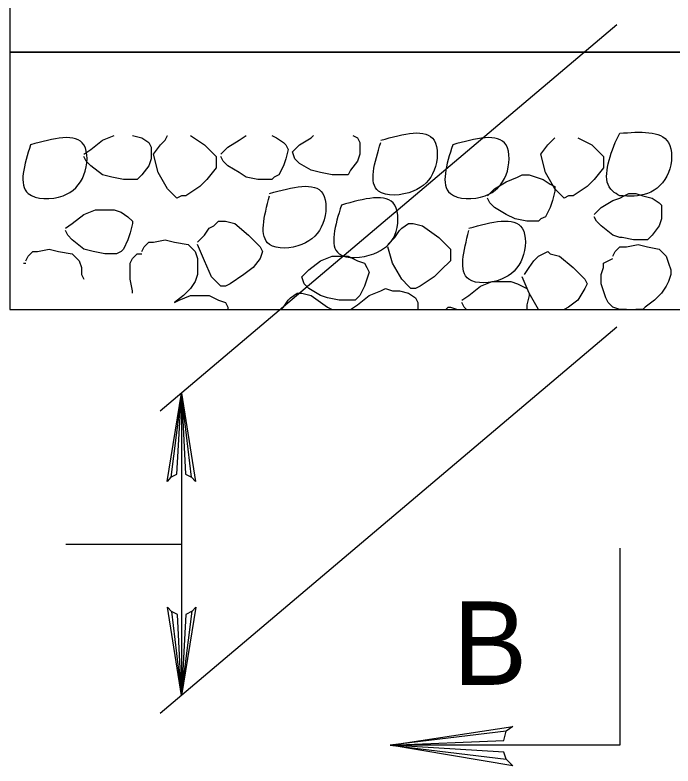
# Model space of a CAD drawing. Extents: x 593 to 1473, y 721 to 1315.
# Drawn here: x 787.25 to 822.71, y 811.39 to 851.89 of the extents above; entities that cross this region are included whole.
import ezdxf

# ---------------------------------------------------------------- set-up
doc = ezdxf.new("R2010")
doc.units = 0
doc.layers.add('1', color=7, linetype='Continuous')
doc.layers.add('2', color=7, linetype='Continuous')

msp = doc.modelspace()

# ---------------------------------------------------------------- linework, layer by layer
at = {"layer": '1'}
for points in [[(795.646, 826.959), (795.975, 827.129), (796.216, 831.5), (795.646, 826.959), (795.447, 826.726), (796.216, 831.5), (796.432, 827.132), (796.757, 826.972), (796.216, 831.5), (796.974, 826.726), (796.757, 826.972)], [(795.646, 826.959), (795.975, 827.129), (796.216, 831.5), (795.646, 826.959), (795.447, 826.726), (796.216, 831.5), (796.432, 827.132), (796.757, 826.972), (796.216, 831.5), (796.974, 826.726), (796.757, 826.972)], [(796.786, 819.732), (796.457, 819.562), (796.216, 815.191), (796.786, 819.732), (796.985, 819.965), (796.216, 815.191), (796, 819.559), (795.675, 819.719), (796.216, 815.191), (795.457, 819.965), (795.675, 819.719)], [(796.786, 819.732), (796.457, 819.562), (796.216, 815.191), (796.786, 819.732), (796.985, 819.965), (796.216, 815.191), (796, 819.559), (795.675, 819.719), (796.216, 815.191), (795.457, 819.965), (795.675, 819.719)]]:
    msp.add_lwpolyline(points, dxfattribs=at)
at = {"layer": '2'}
for p, q in [((819.688, 851.356), (795.071, 830.531)), ((819.584, 845.016), (819.834, 845.516)), ((819.688, 835.048), (795.071, 814.222)), ((796.216, 831.5), (796.216, 815.191)), ((789.993, 823.346), (796.216, 823.346)), ((819.834, 823.141), (819.834, 812.516)), ((819.834, 812.516), (807.459, 812.516))]:
    msp.add_line(p, q, dxfattribs=at)
for points in [[(786.959, 856.891), (786.959, 849.891), (819.834, 849.891)], [(819.834, 849.891), (854.709, 849.891), (854.709, 856.641)], [(819.834, 849.891), (786.959, 849.891), (786.959, 836.016), (819.834, 836.016)], [(819.834, 836.016), (854.709, 836.016), (854.709, 849.891), (819.834, 849.891)], [(791.959, 845.141), (792.584, 845.391)], [(793.584, 845.391), (794.084, 845.266)], [(794.084, 845.266), (794.459, 845.016)], [(795.334, 845.141), (795.459, 845.391)], [(795.459, 845.391), (795.459, 845.391)], [(796.709, 845.391), (797.459, 844.891)], [(799.334, 845.141), (799.709, 845.391)], [(801.084, 845.391), (801.334, 845.266)], [(801.334, 845.266), (801.709, 845.016)], [(802.584, 844.891), (803.209, 845.266)], [(803.209, 845.266), (803.334, 845.391)], [(805.459, 845.391), (805.709, 845.266)], [(805.709, 845.266), (805.834, 845.016)], [(816.209, 845.141), (816.334, 845.266)], [(817.584, 845.266), (818.334, 844.891)], [(791.334, 844.641), (791.959, 845.141)], [(794.459, 845.016), (794.584, 844.766)], [(794.709, 844.391), (795.084, 844.891)], [(795.084, 844.891), (795.334, 845.141)], [(797.459, 844.891), (798.084, 844.266)], [(798.709, 844.766), (799.334, 845.141)], [(801.709, 845.016), (801.834, 844.891)], [(801.834, 844.891), (801.959, 844.641)], [(802.209, 844.516), (802.584, 844.891)], [(805.834, 845.016), (805.834, 844.766)], [(815.584, 844.391), (815.959, 844.891)], [(815.959, 844.891), (816.209, 845.141)], [(818.334, 844.891), (818.959, 844.266)], [(790.959, 844.391), (791.334, 844.641)], [(794.584, 844.766), (794.584, 844.641)], [(794.584, 844.641), (794.584, 844.141)], [(798.334, 844.391), (798.709, 844.766)], [(801.959, 844.641), (801.834, 844.141)], [(802.334, 844.141), (802.209, 844.516)], [(805.834, 844.766), (805.834, 844.391)], [(791.084, 844.016), (790.959, 844.266)], [(794.584, 844.141), (794.459, 843.766)], [(794.959, 843.391), (794.709, 844.391)], [(798.084, 844.266), (798.084, 843.891)], [(798.459, 844.016), (798.334, 844.266)], [(801.834, 844.141), (801.709, 843.766)], [(802.584, 843.891), (802.334, 844.141)], [(805.834, 844.391), (805.709, 844.016)], [(815.834, 843.391), (815.584, 844.391)], [(818.959, 844.266), (818.959, 843.891)], [(791.334, 843.766), (791.084, 844.016)], [(791.959, 843.266), (791.334, 843.766)], [(794.459, 843.766), (794.084, 843.266)], [(798.084, 843.641), (797.584, 843.016)], [(798.084, 843.891), (798.084, 843.641)], [(798.709, 843.766), (798.459, 844.016)], [(799.334, 843.391), (798.709, 843.766)], [(801.709, 843.766), (801.459, 843.266)], [(803.209, 843.516), (802.584, 843.891)], [(805.709, 844.016), (805.334, 843.516)], [(818.959, 843.641), (818.459, 843.016)], [(818.959, 843.891), (818.959, 843.641)], [(792.459, 843.141), (791.959, 843.266)], [(794.084, 843.266), (793.959, 843.141)], [(795.459, 842.516), (794.959, 843.391)], [(799.709, 843.141), (799.334, 843.391)], [(801.459, 843.266), (801.209, 843.141)], [(803.709, 843.391), (803.209, 843.516)], [(804.334, 843.266), (803.709, 843.391)], [(805.084, 843.266), (804.334, 843.266)], [(805.209, 843.266), (805.084, 843.266)], [(805.334, 843.516), (805.209, 843.266)], [(814.334, 843.141), (814.584, 843.266)], [(814.584, 843.266), (814.959, 843.266)], [(814.959, 843.266), (815.334, 843.141)], [(816.334, 842.516), (815.834, 843.391)], [(793.084, 843.016), (792.459, 843.141)], [(793.834, 843.016), (793.084, 843.016)], [(793.959, 843.141), (793.834, 843.016)], [(797.584, 843.016), (797.209, 842.641)], [(800.334, 843.016), (799.709, 843.141)], [(801.084, 843.016), (800.334, 843.016)], [(801.209, 843.141), (801.084, 843.016)], [(813.084, 842.516), (813.709, 842.891)], [(813.709, 842.891), (814.334, 843.141)], [(815.334, 843.141), (815.709, 843.016)], [(815.709, 843.016), (816.084, 842.766)], [(818.459, 843.016), (818.084, 842.641)], [(795.834, 842.141), (795.459, 842.516)], [(797.209, 842.641), (796.459, 842.141)], [(812.709, 842.141), (813.084, 842.516)], [(816.084, 842.766), (816.334, 842.641)], [(816.334, 842.641), (816.334, 842.391)], [(816.709, 842.141), (816.334, 842.516)], [(818.084, 842.641), (817.334, 842.141)], [(795.959, 842.016), (795.834, 842.141)], [(796.209, 842.141), (795.959, 842.016)], [(796.459, 842.141), (796.209, 842.141)], [(812.834, 841.766), (812.709, 842.016)], [(816.334, 842.391), (816.209, 841.891)], [(816.834, 842.016), (816.709, 842.141)], [(817.084, 842.141), (816.834, 842.016)], [(817.334, 842.141), (817.084, 842.141)], [(819.459, 841.891), (819.834, 842.016)], [(819.834, 842.016), (820.084, 842.141)], [(820.084, 842.141), (820.334, 842.266)], [(820.334, 842.266), (820.709, 842.266)], [(820.709, 842.266), (821.084, 842.141)], [(821.084, 842.141), (821.584, 842.016)], [(821.584, 842.016), (821.959, 841.766)], [(813.084, 841.516), (812.834, 841.766)], [(816.209, 841.891), (816.084, 841.516)], [(818.834, 841.516), (819.459, 841.891)], [(821.959, 841.766), (822.084, 841.641)], [(822.084, 841.641), (822.084, 841.391)], [(790.959, 841.141), (791.584, 841.391)], [(791.584, 841.391), (791.834, 841.391)], [(791.834, 841.391), (792.209, 841.391)], [(792.209, 841.391), (792.584, 841.391)], [(792.584, 841.391), (792.959, 841.266)], [(792.959, 841.266), (793.334, 841.016)], [(813.709, 841.141), (813.084, 841.516)], [(816.084, 841.516), (815.834, 841.016)], [(818.459, 841.141), (818.834, 841.516)], [(822.084, 841.391), (822.084, 840.891)], [(790.334, 840.641), (790.959, 841.141)], [(793.334, 841.016), (793.584, 840.766)], [(814.209, 840.891), (813.709, 841.141)], [(814.834, 840.766), (814.209, 840.891)], [(815.584, 840.891), (815.459, 840.766)], [(815.834, 841.016), (815.584, 840.891)], [(818.584, 840.766), (818.459, 841.016)], [(822.084, 840.891), (821.959, 840.516)], [(789.959, 840.391), (790.334, 840.641)], [(793.584, 840.641), (793.459, 840.141)], [(793.584, 840.766), (793.584, 840.641)], [(797.459, 840.016), (797.709, 840.391)], [(797.709, 840.391), (797.959, 840.516)], [(797.959, 840.516), (798.209, 840.766)], [(798.209, 840.766), (798.334, 840.766)], [(798.334, 840.766), (798.584, 840.766)], [(798.584, 840.766), (799.084, 840.641)], [(799.084, 840.641), (799.834, 840.016)], [(807.959, 840.266), (808.084, 840.391)], [(808.084, 840.391), (808.459, 840.641)], [(808.459, 840.641), (808.584, 840.641)], [(808.584, 840.641), (808.709, 840.641)], [(808.709, 840.641), (809.209, 840.516)], [(809.209, 840.516), (810.084, 839.891)], [(815.459, 840.766), (814.834, 840.766)], [(818.834, 840.516), (818.584, 840.766)], [(819.459, 840.016), (818.834, 840.516)], [(821.959, 840.516), (821.584, 840.016)], [(790.084, 840.016), (789.959, 840.266)], [(790.334, 839.766), (790.084, 840.016)], [(793.459, 840.141), (793.334, 839.766)], [(797.084, 839.641), (797.459, 840.016)], [(799.834, 840.016), (800.459, 839.391)], [(807.709, 839.891), (807.959, 840.266)], [(819.834, 839.891), (819.459, 840.016)], [(821.584, 840.016), (821.459, 839.891)], [(790.959, 839.266), (790.334, 839.766)], [(793.334, 839.766), (793.084, 839.266)], [(794.209, 839.391), (794.459, 839.641)], [(794.459, 839.641), (794.709, 839.641)], [(794.709, 839.641), (795.334, 839.766)], [(795.334, 839.766), (795.834, 839.641)], [(795.834, 839.641), (796.584, 839.516)], [(807.334, 839.516), (807.709, 839.891)], [(810.084, 839.891), (810.709, 839.266)], [(819.959, 839.891), (819.834, 839.891)], [(820.584, 839.766), (819.959, 839.891)], [(821.334, 839.766), (820.584, 839.766)], [(821.459, 839.891), (821.334, 839.766)], [(788.459, 839.141), (789.084, 839.266)], [(789.084, 839.266), (789.584, 839.141)], [(791.459, 839.141), (790.959, 839.266)], [(793.084, 839.266), (792.959, 839.141)], [(794.084, 839.141), (794.209, 839.391)], [(796.584, 839.516), (796.834, 839.266)], [(796.834, 839.266), (796.959, 839.141)], [(797.459, 838.641), (797.084, 839.516)], [(800.459, 839.391), (800.584, 839.141)], [(807.584, 838.516), (807.334, 839.391)], [(810.709, 839.266), (810.709, 839.016)], [(819.584, 839.141), (819.834, 839.391)], [(819.834, 839.391), (819.834, 839.391)], [(819.834, 839.391), (820.209, 839.391)], [(820.209, 839.391), (820.834, 839.516)], [(820.834, 839.516), (821.334, 839.391)], [(821.334, 839.391), (821.959, 839.266)], [(821.959, 839.266), (822.209, 839.016)], [(787.834, 838.641), (787.959, 838.891)], [(787.959, 838.891), (788.209, 839.141)], [(788.209, 839.141), (788.459, 839.141)], [(789.584, 839.141), (790.334, 839.016)], [(790.334, 839.016), (790.584, 838.766)], [(790.584, 838.766), (790.709, 838.641)], [(792.084, 839.016), (791.459, 839.141)], [(792.709, 839.016), (792.084, 839.016)], [(792.959, 839.141), (792.709, 839.016)], [(793.459, 838.516), (793.584, 838.766)], [(793.584, 838.766), (793.834, 839.016)], [(793.834, 839.016), (794.084, 839.016)], [(796.959, 839.141), (797.084, 838.766)], [(797.084, 838.766), (797.084, 838.391)], [(800.459, 838.766), (800.084, 838.266)], [(800.584, 839.141), (800.459, 838.766)], [(803.709, 838.641), (804.334, 838.891)], [(804.334, 838.891), (804.584, 838.891)], [(804.584, 838.891), (804.959, 838.891)], [(804.959, 838.891), (805.209, 838.891)], [(805.209, 838.891), (805.709, 838.641)], [(810.709, 839.016), (810.709, 838.641)], [(815.209, 838.641), (815.459, 838.891)], [(815.459, 838.891), (815.709, 839.016)], [(815.709, 839.016), (815.959, 839.141)], [(815.959, 839.141), (816.084, 839.016)], [(816.084, 839.016), (816.584, 838.891)], [(816.584, 838.891), (817.334, 838.266)], [(819.209, 838.641), (819.459, 838.766)], [(819.459, 838.891), (819.584, 839.141)], [(822.209, 839.016), (822.334, 838.891)], [(822.334, 838.891), (822.459, 838.516)], [(787.709, 838.516), (787.834, 838.516)], [(790.709, 838.641), (790.834, 838.266)], [(793.459, 838.141), (793.459, 838.516)], [(797.084, 838.391), (797.084, 838.141)], [(797.834, 837.766), (797.459, 838.641)], [(803.084, 838.141), (803.709, 838.641)], [(805.709, 838.641), (806.084, 838.516)], [(806.084, 838.516), (806.209, 838.266)], [(808.084, 837.641), (807.584, 838.516)], [(810.709, 838.641), (810.209, 838.141)], [(814.959, 838.266), (815.209, 838.641)], [(818.959, 838.516), (819.209, 838.641)], [(818.959, 838.266), (818.959, 838.516)], [(822.459, 838.516), (822.584, 838.141)], [(790.834, 838.266), (790.834, 837.891)], [(793.459, 837.641), (793.459, 838.141)], [(797.084, 838.141), (797.084, 837.891)], [(800.084, 838.266), (799.584, 837.891)], [(802.709, 837.766), (803.084, 838.141)], [(806.209, 838.266), (806.334, 838.016)], [(806.334, 838.016), (806.209, 837.641)], [(810.209, 838.141), (809.834, 837.766)], [(814.709, 837.891), (814.959, 838.266)], [(817.334, 838.266), (817.959, 837.641)], [(818.834, 837.891), (818.959, 838.266)], [(822.584, 838.141), (822.584, 837.891)], [(790.834, 837.891), (790.959, 837.641)], [(790.959, 837.641), (790.959, 837.641)], [(793.584, 837.016), (793.459, 837.641)], [(797.084, 837.891), (796.959, 837.516)], [(798.209, 837.391), (797.834, 837.766)], [(799.584, 837.891), (798.834, 837.391)], [(802.834, 837.391), (802.709, 837.766)], [(806.209, 837.641), (806.084, 837.266)], [(808.459, 837.266), (808.084, 837.641)], [(809.834, 837.766), (809.084, 837.266)], [(814.959, 836.891), (814.584, 837.766)], [(817.959, 837.641), (818.084, 837.391)], [(818.834, 837.391), (818.834, 837.891)], [(822.584, 837.891), (822.459, 837.516)], [(796.709, 837.141), (796.334, 836.766)], [(796.959, 837.516), (796.709, 837.141)], [(798.334, 837.266), (798.209, 837.391)], [(798.584, 837.266), (798.334, 837.266)], [(798.834, 837.391), (798.584, 837.266)], [(803.084, 837.141), (802.834, 837.391)], [(803.709, 836.766), (803.084, 837.141)], [(806.084, 837.266), (805.834, 836.766)], [(806.959, 837.016), (807.209, 837.141)], [(807.209, 837.141), (807.584, 837.016)], [(808.584, 837.141), (808.459, 837.266)], [(808.834, 837.141), (808.584, 837.141)], [(809.084, 837.266), (808.834, 837.141)], [(811.709, 836.766), (812.334, 837.266)], [(812.334, 837.266), (812.959, 837.516)], [(812.959, 837.516), (813.209, 837.516)], [(813.209, 837.516), (813.584, 837.516)], [(813.584, 837.516), (813.959, 837.516)], [(813.959, 837.516), (814.334, 837.391)], [(814.334, 837.391), (814.834, 837.141)], [(814.834, 837.141), (814.959, 836.891)], [(817.959, 837.141), (817.584, 836.516)], [(818.084, 837.391), (817.959, 837.141)], [(819.084, 836.641), (818.834, 837.391)], [(822.334, 837.266), (822.084, 836.891)], [(822.459, 837.516), (822.334, 837.266)], [(793.584, 836.891), (793.584, 837.016)], [(796.334, 836.766), (795.834, 836.391)], [(796.084, 836.516), (796.709, 836.766)], [(796.709, 836.766), (796.959, 836.766)], [(796.959, 836.766), (797.334, 836.766)], [(797.334, 836.766), (797.709, 836.766)], [(797.709, 836.766), (798.209, 836.516)], [(802.084, 836.641), (802.459, 836.891)], [(802.459, 836.891), (802.584, 836.891)], [(802.584, 836.891), (802.709, 836.891)], [(802.709, 836.891), (803.209, 836.766)], [(803.209, 836.766), (804.084, 836.141)], [(804.084, 836.641), (803.709, 836.766)], [(805.834, 836.766), (805.584, 836.516)], [(805.709, 836.266), (806.334, 836.766)], [(806.334, 836.766), (806.959, 837.016)], [(807.584, 837.016), (807.959, 837.016)], [(807.959, 837.016), (808.459, 836.891)], [(808.459, 836.891), (808.834, 836.641)], [(811.334, 836.516), (811.709, 836.766)], [(814.959, 836.766), (814.834, 836.266)], [(815.459, 836.016), (814.959, 836.891)], [(814.959, 836.891), (814.959, 836.766)], [(822.084, 836.891), (821.709, 836.516)], [(795.834, 836.391), (796.084, 836.516)], [(795.834, 836.391), (795.834, 836.391)], [(798.209, 836.516), (798.584, 836.391)], [(798.584, 836.391), (798.709, 836.141)], [(801.709, 836.141), (801.959, 836.516)], [(801.959, 836.516), (802.084, 836.641)], [(804.709, 836.516), (804.084, 836.641)], [(805.459, 836.516), (804.709, 836.516)], [(805.584, 836.516), (805.459, 836.516)], [(808.834, 836.641), (808.959, 836.391)], [(808.959, 836.391), (808.959, 836.266)], [(811.459, 836.141), (811.334, 836.391)], [(817.584, 836.516), (817.084, 836.141)], [(819.209, 836.391), (819.084, 836.641)], [(819.459, 836.141), (819.209, 836.391)], [(821.709, 836.516), (821.209, 836.141)], [(798.709, 836.141), (798.709, 836.016)], [(798.709, 836.016), (798.709, 836.016)], [(801.584, 836.016), (801.709, 836.141)], [(804.084, 836.141), (804.334, 836.016)], [(805.334, 836.016), (805.709, 836.266)], [(808.959, 836.266), (808.959, 836.016)], [(810.334, 836.016), (810.459, 836.016)], [(810.459, 836.016), (810.584, 836.141)], [(810.584, 836.141), (810.709, 836.141)], [(810.709, 836.141), (811.084, 836.016)], [(811.584, 836.016), (811.459, 836.141)], [(814.834, 836.266), (814.834, 836.016)], [(815.459, 836.016), (815.459, 836.016)], [(817.084, 836.141), (816.834, 836.016)], [(819.834, 836.016), (819.459, 836.141)], [(819.834, 836.016), (819.834, 836.016)], [(820.209, 836.016), (819.834, 836.016)], [(821.084, 836.016), (820.709, 836.016)], [(821.209, 836.141), (821.084, 836.016)], [(813.709, 811.766), (813.584, 812.141), (807.459, 812.516), (813.709, 811.766), (814.084, 811.391), (807.459, 812.516), (813.584, 812.766), (813.709, 813.266), (807.459, 812.516), (814.084, 813.516), (813.709, 813.266)]]:
    msp.add_lwpolyline(points, dxfattribs=at)
for points in [[(806.959, 845.141), (809.834, 845.141), (809.834, 843.516), (808.709, 842.391), (806.834, 842.391), (806.959, 845.016)], [(819.834, 845.516), (822.459, 845.016), (822.459, 843.391), (821.334, 842.266), (819.834, 842.141)], [(788.084, 844.891), (790.959, 844.891), (790.959, 843.266), (789.834, 842.141), (787.959, 842.266), (788.084, 844.891)], [(810.834, 844.891), (813.709, 844.891), (813.709, 843.266), (812.584, 842.141), (810.709, 842.266), (810.834, 844.891)], [(819.834, 842.141), (819.459, 842.391), (819.584, 845.016)], [(800.959, 842.266), (803.834, 842.266), (803.834, 840.641), (802.709, 839.516), (800.959, 839.516), (800.959, 842.141)], [(804.834, 841.641), (807.709, 841.641), (807.709, 840.016), (806.584, 839.016), (804.709, 839.016), (804.834, 841.641)], [(811.709, 840.391), (814.584, 840.391), (814.584, 838.766), (813.459, 837.641), (811.709, 837.641), (811.709, 840.266)]]:
    msp.add_spline(points, degree=3, dxfattribs=at)

# ---------------------------------------------------------------- texts
msp.add_text('B', height=4.5, dxfattribs=at).set_placement((810.834, 815.766))

doc.saveas('drawing.dxf')
